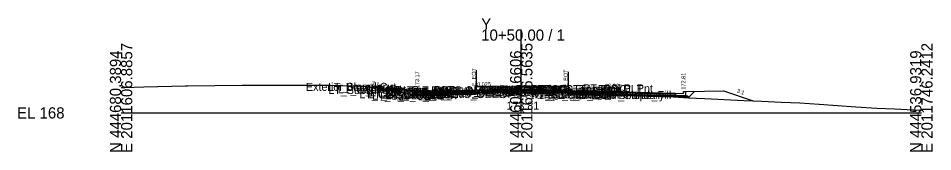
# Model space of a CAD drawing. Extents: x -26 to 3203, y -10 to 9532.
# Drawn here: x -25.7 to 202.8, y 4490.3 to 4523.6 of the extents above; entities that cross this region are included whole.
import ezdxf

# ---------------------------------------------------------------- set-up
doc = ezdxf.new("R2010")
doc.units = 0
for name, color, linetype in [('Default', 7, 'Continuous'), ('Exist CMT Pavement', 7, 'Continuous'), ('Exist Cross Section Cell', 7, 'Continuous'), ('Exist XS Center Line Elevation Label', 7, 'Continuous'), ('Exist XS Ground Line', 7, 'Continuous'), ('Prop CMT Conc Surface', 7, 'Continuous'), ('Prop CMT Concrete Structures', 7, 'Continuous'), ('Prop CMT Pvmt Course 1', 7, 'Continuous'), ('Prop CMT Pvmt Course 1 CG', 7, 'Continuous'), ('Prop CMT Pvmt Course 1 Wedge', 7, 'Continuous'), ('Prop CMT Pvmt Course 2', 7, 'Continuous'), ('Prop CMT Pvmt Course 2 Wedge', 7, 'Continuous'), ('Prop CMT Pvmt Course 3', 7, 'Continuous'), ('Prop CMT Pvmt Surface', 7, 'Continuous'), ('Prop CMT Pvmt Wedge Surface 1', 7, 'Continuous'), ('Prop CMT Pvmt Wedge Surface 2', 7, 'Continuous'), ('Prop CMT Pvmt Wedge Surface 3', 7, 'Continuous'), ('Prop CMT Slope Grass', 7, 'Continuous'), ('Prop CMT Subgrade Earthwork', 7, 'Continuous'), ('Prop XS Hydro Elevations', 7, 'Continuous'), ('Prop XS Label Text', 7, 'Continuous'), ('Prop XS SE Text', 7, 'Continuous'), ('Prop XS Side Slope Text', 7, 'Continuous'), ('Scratch_Level_0', 7, 'Continuous')]:
    doc.layers.add(name, color=color, linetype=linetype)

msp = doc.modelspace()

# ---------------------------------------------------------------- linework, layer by layer
at = {"layer": 'Exist CMT Pavement'}
for points in [[(100, 4505.81), (88.74, 4505.64)], [(100, 4505.81), (98.06, 4505.8), (97.07, 4505.79), (94.58, 4505.77), (93.39, 4505.76), (91.12, 4505.71), (90.1, 4505.69), (89.16, 4505.68), (88.96, 4505.66), (88.75, 4505.64), (88.74, 4505.64)], [(100, 4505.81), (100.2, 4505.81), (101.31, 4505.76), (101.41, 4505.75), (101.48, 4505.75), (101.53, 4505.75), (101.78, 4505.74), (105.01, 4505.64), (107.86, 4505.52), (108.49, 4505.49), (111.32, 4505.34), (111.73, 4505.3)]]:
    msp.add_lwpolyline(points, dxfattribs=at)
at = {"layer": 'Exist Cross Section Cell'}
for p, q in [((100, 4500), (100, 4520.84)), ((0, 4500), (100, 4500)), ((100, 4500), (200, 4500))]:
    msp.add_line(p, q, dxfattribs=at)
at = {"layer": 'Exist XS Ground Line'}
msp.add_lwpolyline([(0, 4506.33), (0.9, 4506.37), (5.65, 4506.48), (16.1, 4506.75), (16.62, 4506.76), (30.22, 4506.92), (30.59, 4506.94), (30.97, 4506.94), (44.17, 4506.94), (44.74, 4506.93), (45.32, 4506.94), (51.81, 4506.95), (58.11, 4506.76), (58.88, 4506.74), (72.47, 4505.74), (75.08, 4505.52), (78.46, 4505.54), (88.75, 4505.64), (89.16, 4505.68), (90.1, 4505.69), (91.12, 4505.71), (93.39, 4505.76), (94.58, 4505.77), (97.07, 4505.79), (98.06, 4505.8), (100.2, 4505.81), (100.98, 4505.77), (101.53, 4505.75), (104.29, 4505.66), (104.65, 4505.65), (105.01, 4505.64), (107.86, 4505.52), (108.49, 4505.49), (111.32, 4505.34), (111.73, 4505.3), (113.22, 4505.06), (127.29, 4504.56), (131.44, 4504.43), (136.68, 4504.06), (141.77, 4503.78), (145.8, 4503.57), (155.71, 4503.12), (157.9, 4503.01), (160.15, 4502.91), (164.97, 4502.68), (169.65, 4502.5), (174.5, 4502.19), (183.6, 4501.52), (188.86, 4501.21), (193.26, 4501.03), (196.46, 4500.83), (200, 4500.67)], dxfattribs=at)
at = {"layer": 'Prop CMT Conc Surface'}
for points in [[(74, 4505.17), (74, 4505.67), (73.5, 4505.67)], [(76, 4505.3), (74, 4505.17)], [(138.53, 4504.94), (140.53, 4504.81)], [(140.53, 4504.81), (140.53, 4505.31), (141.03, 4505.31)]]:
    msp.add_lwpolyline(points, dxfattribs=at)
at = {"layer": 'Prop CMT Concrete Structures'}
for points in [[(76, 4505.3), (74, 4505.17), (74, 4505.67), (73.5, 4505.67)], [(73.5, 4505.67), (73.5, 4504.65), (76, 4504.72)], [(76, 4504.72), (76, 4505.3)], [(138.53, 4504.94), (140.53, 4504.81), (140.53, 4505.31), (141.03, 4505.31)], [(141.03, 4505.31), (141.03, 4504.29), (138.53, 4504.35)], [(138.53, 4504.35), (138.53, 4504.94)]]:
    msp.add_lwpolyline(points, dxfattribs=at)
at = {"layer": 'Prop CMT Pvmt Course 1'}
for points in [[(100, 4505.9), (76, 4505.3)], [(76, 4505.05), (88.74, 4505.37)], [(76, 4505.3), (76, 4505.05)], [(88.74, 4505.49), (100, 4505.77)], [(88.74, 4505.37), (88.74, 4505.49)], [(100, 4505.9), (138.53, 4504.94)], [(100, 4505.65), (100, 4505.9)], [(100, 4505.65), (100, 4505.9)], [(111.73, 4505.48), (100, 4505.77)], [(100, 4505.77), (100, 4505.65), (100, 4505.65)], [(100, 4505.77), (100, 4505.65), (100, 4505.65)], [(111.73, 4505.36), (111.73, 4505.48)], [(138.53, 4504.69), (138.5, 4504.69)], [(138.53, 4504.94), (138.53, 4504.69)]]:
    msp.add_lwpolyline(points, dxfattribs=at)
at = {"layer": 'Prop CMT Pvmt Course 1 CG'}
for points in [[(76, 4504.72), (73, 4504.64), (72.66, 4504.3)], [(72.66, 4504.3), (76, 4504.38)], [(76, 4504.38), (76, 4504.72)], [(141.87, 4503.94), (111.73, 4504.69)], [(138.53, 4504.35), (141.53, 4504.28), (141.87, 4503.94)], [(138.53, 4504.02), (138.53, 4504.35)]]:
    msp.add_lwpolyline(points, dxfattribs=at)
at = {"layer": 'Prop CMT Pvmt Course 1 Wedge'}
msp.add_lwpolyline([(100, 4505.77), (111.73, 4505.48)], dxfattribs=at)
at = {"layer": 'Prop CMT Pvmt Course 2'}
for points in [[(88.74, 4505.37), (76, 4505.05)], [(76, 4505.05), (76, 4504.72)], [(76, 4504.72), (88.74, 4505.03)], [(88.74, 4505.03), (88.74, 4505.37)], [(111.73, 4505.02), (111.73, 4505.36)], [(111.73, 4505.36), (138.53, 4504.69)], [(138.53, 4504.69), (138.53, 4504.35)], [(138.53, 4504.35), (138.5, 4504.35)]]:
    msp.add_lwpolyline(points, dxfattribs=at)
at = {"layer": 'Prop CMT Pvmt Course 2 Wedge'}
msp.add_lwpolyline([(110.27, 4505.39), (111.73, 4505.36)], dxfattribs=at)
msp.add_lwpolyline([(110.27, 4505.39), (111.73, 4505.36)], dxfattribs=at)
at = {"layer": 'Prop CMT Pvmt Course 3'}
for points in [[(88.74, 4505.03), (76, 4504.72)], [(76, 4504.72), (76, 4504.38)], [(76, 4504.38), (88.74, 4504.7)], [(88.74, 4504.7), (88.74, 4505.03)], [(111.73, 4505.02), (138.53, 4504.35)], [(111.73, 4504.69), (111.73, 4505.02)], [(138.53, 4504.02), (138.5, 4504.02)], [(138.53, 4504.35), (138.53, 4504.02)]]:
    msp.add_lwpolyline(points, dxfattribs=at)
at = {"layer": 'Prop CMT Pvmt Surface'}
for points in [[(100, 4505.9), (76, 4505.3)], [(100, 4505.9), (138.53, 4504.94)]]:
    msp.add_lwpolyline(points, dxfattribs=at)
at = {"layer": 'Prop CMT Pvmt Wedge Surface 1'}
for points in [[(88.74, 4505.37), (76, 4505.05)], [(76, 4505.05), (76, 4505.3)], [(100, 4505.77), (88.74, 4505.49)], [(88.74, 4505.49), (88.74, 4505.37)], [(100, 4505.77), (111.73, 4505.48)], [(111.73, 4505.48), (111.73, 4505.36)], [(138.5, 4504.69), (138.53, 4504.69)], [(138.53, 4504.69), (138.53, 4504.94)]]:
    msp.add_lwpolyline(points, dxfattribs=at)
at = {"layer": 'Prop CMT Pvmt Wedge Surface 2'}
for points in [[(100, 4505.65), (76, 4505.05)], [(76, 4505.05), (76, 4505.3)], [(100, 4505.65), (111.73, 4505.36)], [(138.53, 4504.69), (138.53, 4504.94)]]:
    msp.add_lwpolyline(points, dxfattribs=at)
at = {"layer": 'Prop CMT Pvmt Wedge Surface 3'}
for points in [[(100, 4505.32), (76, 4504.72)], [(76, 4504.72), (76, 4505.3)], [(100, 4505.32), (111.73, 4505.02)], [(138.53, 4504.35), (138.53, 4504.94)]]:
    msp.add_lwpolyline(points, dxfattribs=at)
at = {"layer": 'Prop CMT Slope Grass'}
for points in [[(73.5, 4505.67), (64, 4505.86), (62.06, 4506.51)], [(141.03, 4505.31), (150.53, 4505.5), (158, 4503.01)]]:
    msp.add_lwpolyline(points, dxfattribs=at)
at = {"layer": 'Prop CMT Subgrade Earthwork'}
for points in [[(76, 4504.38), (72.66, 4504.3), (71.24, 4505.71)], [(88.74, 4504.7), (76, 4504.38)], [(88.74, 4504.7), (88.76, 4505.64)], [(111.73, 4504.69), (141.87, 4503.94), (143.28, 4505.35)], [(111.73, 4504.69), (111.73, 4505.3)], [(138.5, 4504.02), (138.53, 4504.02)]]:
    msp.add_lwpolyline(points, dxfattribs=at)
at = {"layer": 'Prop XS Label Text'}
for p, q in [((88.76, 4510.64), (88.76, 4505.64)), ((111.73, 4510.3), (111.73, 4505.3))]:
    msp.add_line(p, q, dxfattribs=at)

# ---------------------------------------------------------------- texts
at = {"layer": 'Default'}
msp.add_text('-', height=0.0001, dxfattribs=at).set_placement((0, 4500))
at = {"layer": 'Exist Cross Section Cell'}
for s, p in [('Y', (90, 4520.84)), ('10+50.00 / 1', (90, 4518.04)), ('EL 168', (-26, 4498.6))]:
    msp.add_text(s, height=2.8, dxfattribs=at).set_placement(p)
for s, p in [('E 2011606.8857', (2.8, 4490)), ('E 2011676.5635', (102.8, 4490)), ('E 2011746.2412', (202.8, 4490)), ('N 444680.3894', (0, 4490)), ('N 444608.6606', (100, 4490)), ('N 444536.9319', (200, 4490))]:
    msp.add_text(s, height=2.8, rotation=90, dxfattribs=at).set_placement(p)
at = {"layer": 'Exist XS Center Line Elevation Label'}
msp.add_text('173.81', height=2, dxfattribs=at).set_placement((96.32, 4500.81))
at = {"layer": 'Prop XS Hydro Elevations'}
for s, p in [('173.17', (74.5, 4506.17)), ('172.81', (141.03, 4505.81))]:
    msp.add_text(s, height=1, rotation=90, dxfattribs=at).set_placement(p)
at = {"layer": 'Prop XS Label Text'}
for p in [(88.66, 4506.67), (111.63, 4506.32)]:
    msp.add_text('E. EOT', height=1, rotation=90, dxfattribs=at).set_placement(p)
at = {"layer": 'Prop XS SE Text'}
for rotation, p in [(1.4321, (88.98, 4506.62)), (358.5679, (121.72, 4506.33))]:
    msp.add_text('0.025', height=1, rotation=rotation, dxfattribs=at).set_placement(p)
at = {"layer": 'Prop XS Side Slope Text'}
for p in [(62.51, 4507.14), (153.8, 4505.11)]:
    msp.add_text('3:1', height=1, rotation=341.5651, dxfattribs=at).set_placement(p)
at = {"layer": 'Scratch_Level_0'}
for s, p in [('Exterior Boundary', (46.2, 4505.51)), ('LT_Slope_Cut', (51.7, 4505.51)), ('LT_Sub_Trench_Out_DLT', (51.81, 4504.71)), ('LT_CSLP_Pnt', (54.17, 4504.86)), ('LT_CG_Top_Face', (61.26, 4504.67)), ('LT_CG_Top_BOC', (61.78, 4504.67)), ('LT_PV_Sub_Tie_Out', (73.7, 4504.64)), ('LT_PV_OEEOP_EG', (76.29, 4504.64)), ('RT_PV_IEEOP_EG', (88.14, 4504.81)), ('LT_PV_IEEOP_EG', (88.19, 4504.81)), ('RT_PV2_IEEOP', (89.91, 4504.65)), ('LT_PV2_IEEOP', (89.95, 4504.65)), ('RT_PV1_IEEOP', (90.47, 4504.77)), ('LT_PV1_IEEOP', (90.52, 4504.77)), ('PV2_PGL', (93.91, 4504.65)), ('PV1_PGL', (94.47, 4504.9)), ('RT_Sub_Trench_Out_DLT', (98.52, 4504.98)), ('RT_CG_Top_Face', (102.45, 4504.94)), ('RT_CG_Top_BOC', (103.98, 4504.94)), ('RT_CSLP_Pnt', (115.37, 4505.13)), ('LT_CG1_Shelf_Out', (59.55, 4503.64)), ('LT_CG_Bot_BOC', (61.81, 4503.65)), ('LT_CG_Top_Gut', (62.24, 4504.17)), ('LT_Sub_OEOP', (62.77, 4503.3)), ('LT_CG_Bot_IE', (65.91, 4503.72)), ('LT_Sub_OEOT', (66.08, 4503.38)), ('LT_PV2_OEOT', (66.17, 4504.05)), ('LT_PV3_OEOT', (66.17, 4503.72)), ('LT_PV1_OEOT', (66.74, 4504.3)), ('LT_Sub_OEEOP', (77.96, 4503.7)), ('LT_PV2_OEEOP', (78.05, 4504.37)), ('LT_PV3_OEEOP', (78.05, 4504.03)), ('LT_PV1_OEEOP', (78.62, 4504.49)), ('RT_PV3_IEEOP', (89.91, 4504.32)), ('LT_PV3_IEEOP', (89.95, 4504.32)), ('RT_PV_Sub_Tie_Out', (98.1, 4504.06)), ('RT_PV_OEEOP_EG', (100.71, 4504.06)), ('RT_Sub_OEEOP', (102.38, 4503.65)), ('RT_PV2_OEEOP', (102.48, 4504.32)), ('RT_PV3_OEEOP', (102.48, 4503.99)), ('RT_CG1_Shelf_Out', (102.75, 4503.91)), ('RT_PV1_OEEOP', (103.05, 4504.44)), ('RT_CG_Bot_IE', (103.11, 4503.98)), ('RT_Sub_OEOT', (103.27, 4503.65)), ('RT_PV2_OEOT', (103.37, 4504.32)), ('RT_PV3_OEOT', (103.37, 4503.98)), ('RT_CG_Top_Gut', (103.43, 4504.44)), ('RT_PV1_OEOT', (103.93, 4504.57)), ('RT_CG_Bot_BOC', (104.01, 4503.92)), ('RT_Sub_OEOP', (106.65, 4503.57)), ('Exterior Boundary', (114.37, 4503.46)), ('RT_Slope_Fill', (120.7, 4503.46))]:
    msp.add_text(s, height=2, dxfattribs=at).set_placement(p)

doc.saveas('drawing.dxf')
